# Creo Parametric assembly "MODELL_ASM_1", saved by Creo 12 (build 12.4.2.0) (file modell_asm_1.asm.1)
Units: Custom; MM, KILOGRAM, SECS

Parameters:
  PTC_WM_ITERATION = "0"
  PTC_WM_VERSION = "-.0"
  PTC_WM_LIFECYCLE_STATE = "In Work"
  PTC_WM_LIFECYCLE = "MO_CADDocument"
  PTC_WM_CREATED_BY = "Maximilian Roepper (Z0017RMS: MO)"
  PTC_WM_CREATED_ON = "18-Sep-26 11:36:42 AM"
  PTC_WM_MODIFIED_BY = "Maximilian Roepper (Z0017RMS: MO)"
  PTC_WM_MODIFIED_ON = "18-Sep-26 11:36:46 AM"
  PDMLINKNUMBER = "PDM000071454865"
  PTC_WM_NUMBER = "PDM000071454865"

Other parameters: WEIGHT, WEIGHT_FACTOR, WEIGHT_ADD, MC_ERRORS, SUPPLIER

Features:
  1. coordinate system
  2. imported feature
  3. component "RESISTOR_SMD_203_ASM_ASM_1_AS_1"
  4. component "RESISTOR_SMD_822_ASM_ASM_1_AS_1"
  5. component "RESISTOR_SMD_122_ASM_ASM_1_AS_1"
  6. component "RESISTOR_SMD_122_ASM_ASM_1_AS_1"
  7. component "CAPACITOR_805_ASM_ASM_1_ASM_A_1"
  8. component "CAPACITOR_805_1_ASM_ASM_1_ASM_1"
  9. component "CAPACITOR_805_1_ASM_ASM_1_ASM_1"
  10. component "CAPACITOR_805_1_ASM_ASM_1_ASM_1"
  11. component "CAPACITOR_805_1_ASM_ASM_1_ASM_1"
  12. component "PIN_HEADER_MALE_01X04_P2_54MM_1"
  13. component "K_X_F6RPER1_PRT_1_PRT_1"
  14. component "K_X_F6RPER175_PRT_1_PRT_1"
  15. component "K_X_F6RPER176_PRT_1_PRT_1"
  16. component "K_X_F6RPER177_PRT_1_PRT_1"
  17. component "K_X_F6RPER178_PRT_1_PRT_1"
  18. component "K_X_F6RPER179_PRT_1_PRT_1"
  19. component "K_X_F6RPER180_PRT_1_PRT_1"
  20. component "K_X_F6RPER181_PRT_1_PRT_1"
  21. component "K_X_F6RPER182_PRT_1_PRT_1"
  22. component "K_X_F6RPER183_PRT_1_PRT_1"
  23. component "K_X_F6RPER184_PRT_1_PRT_1"
  24. component "K_X_F6RPER185_PRT_1_PRT_1"
  25. component "K_X_F6RPER186_PRT_1_PRT_1"
  26. component "K_X_F6RPER187_PRT_1_PRT_1"
  27. component "K_X_F6RPER188_PRT_1_PRT_1"
  28. component "K_X_F6RPER189_PRT_1_PRT_1"
  29. component "K_X_F6RPER190_PRT_1_PRT_1"
  30. component "K_X_F6RPER191_PRT_1_PRT_1"
  31. component "K_X_F6RPER192_PRT_1_PRT_1"
  32. component "K_X_F6RPER193_PRT_1_PRT_1"
  33. component "K_X_F6RPER194_PRT_1_PRT_1"
  34. component "K_X_F6RPER195_PRT_1_PRT_1"
  35. component "K_X_F6RPER196_PRT_1_PRT_1"
  36. component "K_X_F6RPER197_PRT_1_PRT_1"
  37. component "K_X_F6RPER198_PRT_1_PRT_1"
  38. component "K_X_F6RPER199_PRT_1_PRT_1"
  39. component "K_X_F6RPER200_PRT_1_PRT_1"
  40. component "K_X_F6RPER201_PRT_1_PRT_1"
  41. component "K_X_F6RPER202_PRT_1_PRT_1"
  42. component "K_X_F6RPER203_PRT_1_PRT_1"
  43. component "K_X_F6RPER204_PRT_1_PRT_1"
  44. component "K_X_F6RPER205_PRT_1_PRT_1"
  45. component "K_X_F6RPER206_PRT_1_PRT_1"
  46. component "K_X_F6RPER207_PRT_1_PRT_1"
  47. component "K_X_F6RPER208_PRT_1_PRT_1"
  48. component "K_X_F6RPER209_PRT_1_PRT_1"
  49. component "K_X_F6RPER210_PRT_1_PRT_1"
  50. component "K_X_F6RPER211_PRT_1_PRT_1"
  51. component "K_X_F6RPER212_PRT_1_PRT_1"
  52. component "K_X_F6RPER213_PRT_1_PRT_1"
  53. component "K_X_F6RPER214_PRT_1_PRT_1"
  54. component "K_X_F6RPER215_PRT_1_PRT_1"
  55. component "K_X_F6RPER216_PRT_1_PRT_1"
  56. component "K_X_F6RPER217_PRT_1_PRT_1"
  57. component "K_X_F6RPER218_PRT_1_PRT_1"
  58. component "K_X_F6RPER219_PRT_1_PRT_1"
  59. component "K_X_F6RPER220_PRT_1_PRT_1"
  60. component "K_X_F6RPER221_PRT_1_PRT_1"
  61. component "K_X_F6RPER222_PRT_1_PRT_1"
  62. component "K_X_F6RPER223_PRT_1_PRT_1"
  63. component "K_X_F6RPER224_PRT_1_PRT_1"
  64. component "K_X_F6RPER225_PRT_1_PRT_1"
  65. component "PS-25-5G-WS_1_PRT_1"

Other named items: DRW_VIEW_ORG, ROUGH-GROB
